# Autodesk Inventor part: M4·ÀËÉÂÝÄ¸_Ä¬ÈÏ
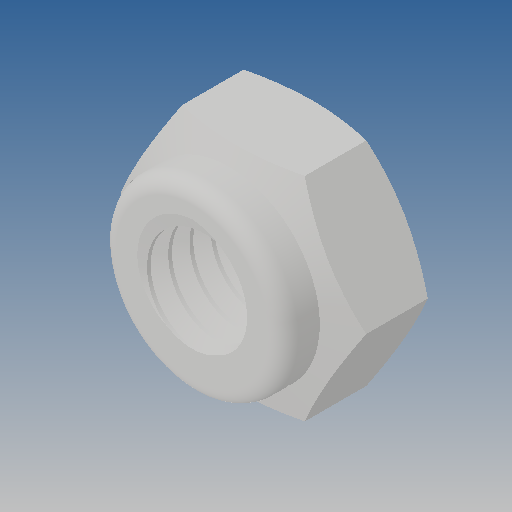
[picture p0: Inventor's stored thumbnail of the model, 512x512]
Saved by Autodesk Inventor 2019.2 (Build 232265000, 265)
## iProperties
Created: 2010-06
Part Number: M4·ÀËÉÂÝÄ¸_Ä¬ÈÏ
Material: Ogólny
Document SubType Name: Modeling
Designer: CADENGINEERING4
Density: 1 g/cm^3
Appearance: Domyślna
Author: CADENGINEERING4
Revision Number: ÈÎºÎ
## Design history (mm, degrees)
feature "NONE"
node "Bryła1"
